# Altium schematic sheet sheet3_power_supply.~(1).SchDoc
size A4; SheetNumber: 2; SheetTotal: 2
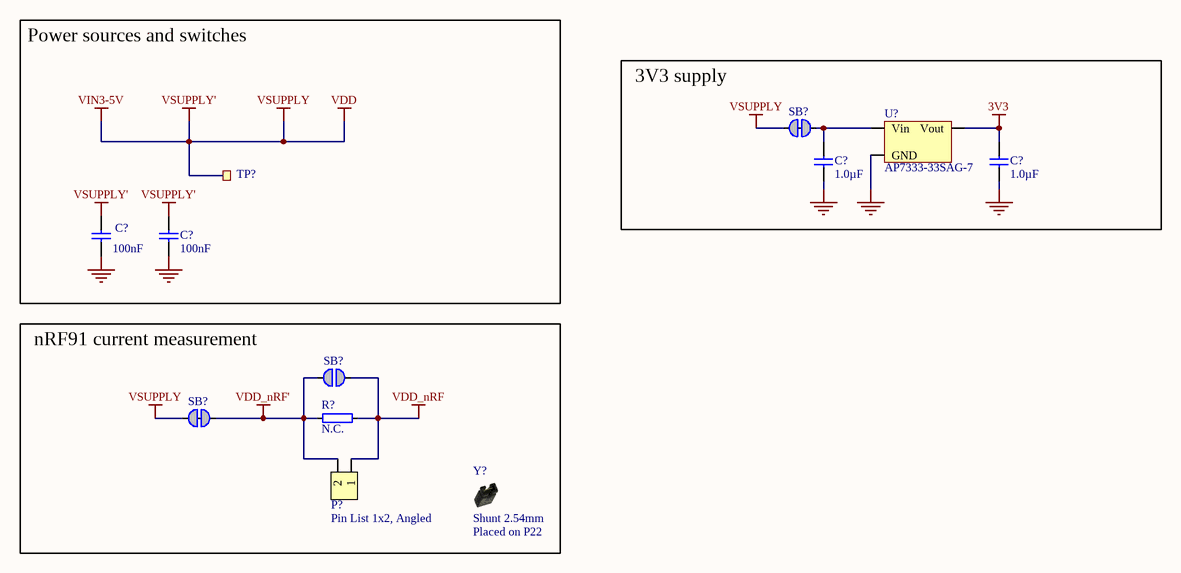
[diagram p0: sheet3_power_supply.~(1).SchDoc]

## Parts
(Parts that share a designator on the sheet are numbered #1, #2 ... from top to bottom, then left to right.)
C?#1  1.0µF  [CAPC0603X03L_C]
C?#2  1.0µF  [CAPC0603X03L_C]
C?#3  100nF  [CAPC0603X03L_C]
C?#4  100nF  [CAPC0603X03L_C]
P?  Pin List 1x2, Angled  [LIST_ANG_1x2-SMD-2.54MM]
R?  N.C.  [RESC1005X04L_NC]
SB?#1  Solderbridge  [Solderbridge_Shorted]  (value not drawn)  (net tie, no BOM)
SB?#2  Solderbridge  [Solderbridge]  (value not drawn)  (no BOM)
SB?#3  Solderbridge  [Solderbridge_Shorted_Power]  (value not drawn)  (net tie, no BOM)
TP?  Ø1.5mm,SMD  [TP_SMD_D1.5mm]  (value not drawn)  (no BOM)
U?  AP7333-33SAG-7  [SOT-23A]
Y?  Shunt 2.54mm  Assembly: Placed on P22  [Shunt_2.54mm_Horizontal]

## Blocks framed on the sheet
Power sources and switches: C?#3 C?#4 TP?
3V3 supply: C?#1 C?#2 SB?#1 U?
nRF91 current measurement: P? R? SB?#2 SB?#3 Y?

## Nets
3V3: C?#2.1 U?.2(Vout)
GND: C?#1.2 C?#2.2 C?#3.2 C?#4.1 U?.3(GND)
VDD: C?#3.1 C?#4.2 SB?#1.2 SB?#3.1 TP?.1  [also labelled VIN3-5V, VSUPPLY, VSUPPLY']
VDD_nRF: P?.1 R?.1 SB?#2.1
VDD_nRF': P?.2 R?.2 SB?#2.2 SB?#3.2
NetC?#1_1: C?#1.1 SB?#1.1 U?.1(Vin)

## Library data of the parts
C?#1 C?#2 = C0201-1µ0: Capacitor, X5R, ±10%; Manufacturer: N.A.; Part number IPS: 00000001723; Note: 10V; Pad Count: 2
C?#3 C?#4 = C0201-100n: Capacitor, X5R, ±10%; Manufacturer: N.A.; Part number IPS: 00000001248, 00000002505; Note: 16V; Pad Count: 2
P? = Pin List Ang 1x2 SMD, 2.54mm: Pin List 1x2, 2.54mm (100mil), Right Angled, SMD; Manufacturer: W-CON; Manufacturer Part Number: 1125B-1102S0Z135R2; Part number IPS: 00000009972; Note: N.A.; Artikkelnr Noca: 55010023; Pad Count: 2
R? = R0402-N.C.: Not mounted; Manufacturer: N.A.; Note: Chip Res; Assembly: Not mounted; Pad Count: 2
SB?#1 = Solderbridge Shorted: Shorted Solderbridge; Manufacturer: N.A.; Pad Count: 2
SB?#2 = Solderbridge: Manufacturer: N.A.; Pad Count: 2
SB?#3 = Solderbridge Shorted Power: Shorted Solderbridge Power; Manufacturer: N.A.; Pad Count: 2
TP? = TP_SMD_Ø1.5MM: 1.5mm circular SMD testpad; Manufacturer: Nordic Semiconductor; Manufacturer Part Number: N.A.; Pad Count: 1
U? = AP7333-33SAG-7: 300mA, Low Quiescent Current, Fast Transient Low Dropout Linear Regulator; Manufacturer: Diodes Incorporated; Part number IPS: 00000001673; Note: N.A.; Artikkelnr Noca: 17039216; Pad Count: 3
Y? = SHUNT JUMPER 2.54mm BLACK GOLD Horizontal (Obsolete): Shunt Jumper 2.54mm Black; Manufacturer: N.A.; Part number IPS: 00000001916; Note: SHUNT JUMPER .1" BLACK GOLD, h=6.00mm, w=5.00mm; Artikkelnr Noca: 56099001; Pad Count: 2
